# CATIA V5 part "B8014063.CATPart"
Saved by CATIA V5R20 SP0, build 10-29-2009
Part number: B8014063
Revision: 8
Definition: design
Nomenclature: B8014063
Source: made
Description: NOT SPECIFIED
Bounding box of the stored display mesh (mm): x -33 to 33, y -33 to 33, z 0 to 63
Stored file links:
  C:\Users\Utente\Desktop\3D files B801\B8014063.CATPart
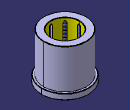
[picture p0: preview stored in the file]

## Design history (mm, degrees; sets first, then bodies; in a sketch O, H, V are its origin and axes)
Body1 "MANIFOLD_SOLID_BREP #38" (main body)
  Solid1: solid without history
Body2 "MANIFOLD_SOLID_BREP #76"
  Solid2: solid without history
Body3 "MANIFOLD_SOLID_BREP #114"
  Solid3: solid without history
Body4 "MANIFOLD_SOLID_BREP #152"
  Solid4: solid without history
Body5 "MANIFOLD_SOLID_BREP #190"
  Solid5: solid without history
Body6 "MANIFOLD_SOLID_BREP #228"
  Solid6: solid without history
Body7 "MANIFOLD_SOLID_BREP #266"
  Solid7: solid without history
Body8 "MANIFOLD_SOLID_BREP #304"
  Solid8: solid without history
Body9 "MANIFOLD_SOLID_BREP #342"
  Solid9: solid without history
Body10 "MANIFOLD_SOLID_BREP #2292"
  Solid10: solid without history
Body11 "MANIFOLD_SOLID_BREP #2330"
  Solid11: solid without history
Body12 "MANIFOLD_SOLID_BREP #2368"
  Solid12: solid without history
Body13 "MANIFOLD_SOLID_BREP #2406"
  Solid13: solid without history
Body14 "MANIFOLD_SOLID_BREP #2444"
  Solid14: solid without history
Body15 "MANIFOLD_SOLID_BREP #2482"
  Solid15: solid without history
Body16 "MANIFOLD_SOLID_BREP #2520"
  Solid16: solid without history
Body17 "MANIFOLD_SOLID_BREP #2558"
  Solid17: solid without history
Body18 "MANIFOLD_SOLID_BREP #2596"
  Solid18: solid without history
Body19 "MANIFOLD_SOLID_BREP #2634"
  Solid19: solid without history
Body20 "MANIFOLD_SOLID_BREP #2672"
  Solid20: solid without history
Body21 "MANIFOLD_SOLID_BREP #2710"
  Solid21: solid without history
Body22 "MANIFOLD_SOLID_BREP #2748"
  Solid22: solid without history
Body23 "MANIFOLD_SOLID_BREP #2786"
  Solid23: solid without history
Body24 "MANIFOLD_SOLID_BREP #2824"
  Solid24: solid without history
Body25 "MANIFOLD_SOLID_BREP #2862"
  Solid25: solid without history
Body26 "MANIFOLD_SOLID_BREP #2900"
  Solid26: solid without history
Body27 "MANIFOLD_SOLID_BREP #2938"
  Solid27: solid without history
Body28 "MANIFOLD_SOLID_BREP #2976"
  Solid28: solid without history
Body29 "MANIFOLD_SOLID_BREP #3014"
  Solid29: solid without history
Body30 "MANIFOLD_SOLID_BREP #3052"
  Solid30: solid without history
Body31 "MANIFOLD_SOLID_BREP #3090"
  Solid31: solid without history
Body32 "MANIFOLD_SOLID_BREP #3128"
  Solid32: solid without history
Body33 "MANIFOLD_SOLID_BREP #3166"
  Solid33: solid without history
Body34 "MANIFOLD_SOLID_BREP #3204"
  Solid34: solid without history
Body35 "MANIFOLD_SOLID_BREP #3242"
  Solid35: solid without history
Body36 "MANIFOLD_SOLID_BREP #3280"
  Solid36: solid without history
Body37 "MANIFOLD_SOLID_BREP #3318"
  Solid37: solid without history
Body38 "MANIFOLD_SOLID_BREP #3356"
  Solid38: solid without history
Body39 "MANIFOLD_SOLID_BREP #3394"
  Solid39: solid without history
Body40 "MANIFOLD_SOLID_BREP #3432"
  Solid40: solid without history
Body41 "MANIFOLD_SOLID_BREP #3470"
  Solid41: solid without history
Body42 "MANIFOLD_SOLID_BREP #3508"
  Solid42: solid without history
Body43 "MANIFOLD_SOLID_BREP #3546"
  Solid43: solid without history
Body44 "MANIFOLD_SOLID_BREP #3584"
  Solid44: solid without history
Body45 "MANIFOLD_SOLID_BREP #3622"
  Solid45: solid without history
Body46 "MANIFOLD_SOLID_BREP #3660"
  Solid46: solid without history
Body47 "MANIFOLD_SOLID_BREP #3698"
  Solid47: solid without history
Body48 "MANIFOLD_SOLID_BREP #3736"
  Solid48: solid without history
Body49 "MANIFOLD_SOLID_BREP #3774"
  Solid49: solid without history
Body50 "MANIFOLD_SOLID_BREP #3812"
  Solid50: solid without history
Body51 "MANIFOLD_SOLID_BREP #3850"
  Solid51: solid without history
Body52 "MANIFOLD_SOLID_BREP #3888"
  Solid52: solid without history
Body53 "MANIFOLD_SOLID_BREP #3926"
  Solid53: solid without history
Body54 "MANIFOLD_SOLID_BREP #3964"
  Solid54: solid without history
Body55 "MANIFOLD_SOLID_BREP #4002"
  Solid55: solid without history
Body56 "MANIFOLD_SOLID_BREP #4040"
  Solid56: solid without history
Body57 "MANIFOLD_SOLID_BREP #4078"
  Solid57: solid without history
Body58 "MANIFOLD_SOLID_BREP #4116"
  Solid58: solid without history
Body59 "MANIFOLD_SOLID_BREP #4154"
  Solid59: solid without history
Body60 "MANIFOLD_SOLID_BREP #4192"
  Solid60: solid without history
Body61 "MANIFOLD_SOLID_BREP #4230"
  Solid61: solid without history
Body62 "MANIFOLD_SOLID_BREP #4268"
  Solid62: solid without history
Body63 "MANIFOLD_SOLID_BREP #4306"
  Solid63: solid without history
Body64 "MANIFOLD_SOLID_BREP #4344"
  Solid64: solid without history
Body65 "MANIFOLD_SOLID_BREP #4382"
  Solid65: solid without history
Body66 "MANIFOLD_SOLID_BREP #4420"
  Solid66: solid without history
Body67 "MANIFOLD_SOLID_BREP #4458"
  Solid67: solid without history
Body68 "MANIFOLD_SOLID_BREP #4496"
  Solid68: solid without history
Body69 "MANIFOLD_SOLID_BREP #4534"
  Solid69: solid without history
Body70 "MANIFOLD_SOLID_BREP #4572"
  Solid70: solid without history
Body71 "MANIFOLD_SOLID_BREP #4610"
  Solid71: solid without history
Body72 "MANIFOLD_SOLID_BREP #4648"
  Solid72: solid without history
Body73 "MANIFOLD_SOLID_BREP #4686"
  Solid73: solid without history
Body74 "MANIFOLD_SOLID_BREP #4724"
  Solid74: solid without history
Body75 "MANIFOLD_SOLID_BREP #4762"
  Solid75: solid without history
Body76 "MANIFOLD_SOLID_BREP #4800"
  Solid76: solid without history
Body77 "MANIFOLD_SOLID_BREP #4838"
  Solid77: solid without history
Body78 "MANIFOLD_SOLID_BREP #4876"
  Solid78: solid without history
Body79 "MANIFOLD_SOLID_BREP #4914"
  Solid79: solid without history
Body80 "MANIFOLD_SOLID_BREP #4952"
  Solid80: solid without history
Body81 "MANIFOLD_SOLID_BREP #4990"
  Solid81: solid without history
Body82 "MANIFOLD_SOLID_BREP #5028"
  Solid82: solid without history
Body83 "MANIFOLD_SOLID_BREP #5066"
  Solid83: solid without history
Body84 "MANIFOLD_SOLID_BREP #5104"
  Solid84: solid without history
Body85 "MANIFOLD_SOLID_BREP #5142"
  Solid85: solid without history
Body86 "MANIFOLD_SOLID_BREP #5180"
  Solid86: solid without history
Body87 "MANIFOLD_SOLID_BREP #5218"
  Solid87: solid without history
Body88 "MANIFOLD_SOLID_BREP #5256"
  Solid88: solid without history
Body89 "MANIFOLD_SOLID_BREP #5294"
  Solid89: solid without history
Body90 "MANIFOLD_SOLID_BREP #5332"
  Solid90: solid without history
Body91 "MANIFOLD_SOLID_BREP #5370"
  Solid91: solid without history
Body92 "MANIFOLD_SOLID_BREP #5408"
  Solid92: solid without history
Body93 "MANIFOLD_SOLID_BREP #5446"
  Solid93: solid without history
Body94 "MANIFOLD_SOLID_BREP #5484"
  Solid94: solid without history
Body95 "MANIFOLD_SOLID_BREP #5522"
  Solid95: solid without history
Body96 "MANIFOLD_SOLID_BREP #5560"
  Solid96: solid without history
Body97 "MANIFOLD_SOLID_BREP #5598"
  Solid97: solid without history
Body98 "MANIFOLD_SOLID_BREP #5636"
  Solid98: solid without history
Body99 "MANIFOLD_SOLID_BREP #5674"
  Solid99: solid without history
Body100 "MANIFOLD_SOLID_BREP #5712"
  Solid100: solid without history
Body101 "MANIFOLD_SOLID_BREP #5750"
  Solid101: solid without history
Body102 "MANIFOLD_SOLID_BREP #5788"
  Solid102: solid without history
Body103 "MANIFOLD_SOLID_BREP #5826"
  Solid103: solid without history
Body104 "MANIFOLD_SOLID_BREP #5864"
  Solid104: solid without history
Body105 "MANIFOLD_SOLID_BREP #5902"
  Solid105: solid without history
